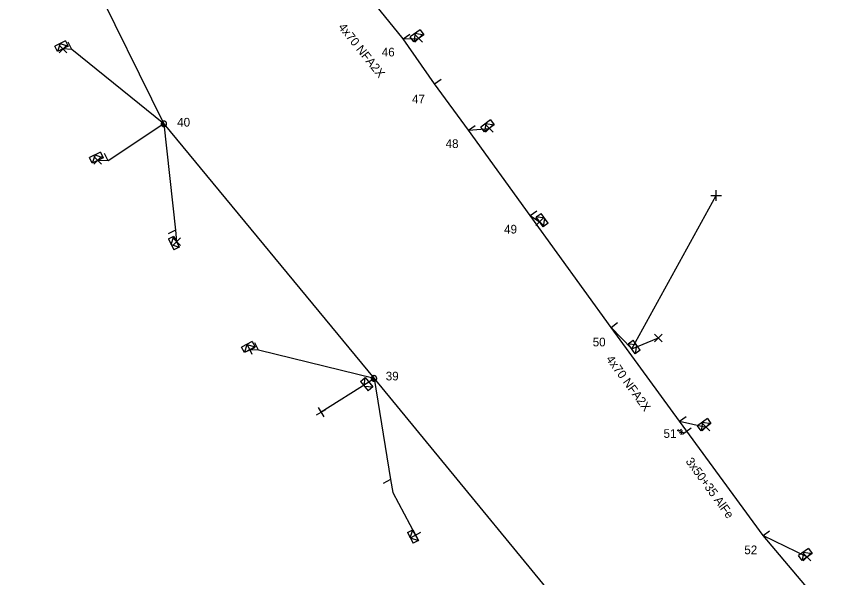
# Model space of a CAD drawing. Extents: x -536148 to -535465, y -1201639 to -1201298.
# Drawn here: x -535704.3 to -535608.3, y -1201422.6 to -1201357.9 of the extents above; entities that cross this region are included whole.
import ezdxf

# ---------------------------------------------------------------- set-up
doc = ezdxf.new("R2010")
doc.units = 0
for name, color, linetype in [('CHRAN_NN', 7, 'Continuous'), ('CIZÍ_NADZEM_POPIS', 7, 'Continuous'), ('CIZÍ_PODZEM', 7, 'Continuous'), ('DOPLŇ_POPISY', 7, 'Continuous'), ('ELE_EON', 7, 'Continuous'), ('ELE_EON_POPIS', 7, 'Continuous'), ('KN_HRAN_POHYBLIVÁ', 7, 'Continuous'), ('KN_VKP_HRAN_NEZNATELNÁ', 7, 'Continuous'), ('KN_VKP_HRAN_SPORNÁ', 7, 'Continuous'), ('NADZEM_NN_IZOL_POPIS', 7, 'Continuous'), ('PB_NN_POPIS', 7, 'Continuous'), ('PLG_EXPORT_GPE', 7, 'Continuous'), ('PODZEM_NN', 7, 'Continuous'), ('RÁMEČEK', 7, 'Continuous')]:
    doc.layers.add(name, color=color, linetype=linetype)

# ---------------------------------------------------------------- blocks, each defined once
blk = doc.blocks.new('NN440')
at = {"layer": 'ELE_EON_POPIS'}
for points in [[(0.63, 0), (0.63, 0.06), (0.62, 0.13), (0.6, 0.19), (0.58, 0.25), (0.55, 0.31), (0.51, 0.37), (0.47, 0.42), (0.42, 0.46), (0.37, 0.51), (0.32, 0.54), (0.26, 0.57), (0.2, 0.59), (0.13, 0.61), (0.07, 0.62), (0, 0.63), (-0.06, 0.62), (-0.13, 0.61), (-0.19, 0.59), (-0.26, 0.57), (-0.31, 0.54), (-0.37, 0.51), (-0.42, 0.46), (-0.47, 0.42), (-0.51, 0.37), (-0.54, 0.31), (-0.57, 0.25), (-0.6, 0.19), (-0.62, 0.13), (-0.63, 0.06), (-0.63, 0), (-0.63, -0.07), (-0.62, -0.14), (-0.6, -0.2), (-0.57, -0.26), (-0.54, -0.32), (-0.51, -0.37), (-0.47, -0.43), (-0.42, -0.47), (-0.37, -0.51), (-0.31, -0.55), (-0.26, -0.58), (-0.19, -0.6), (-0.13, -0.62), (-0.06, -0.63), (0, -0.63), (0.07, -0.63), (0.13, -0.62), (0.2, -0.6), (0.26, -0.58), (0.32, -0.55), (0.37, -0.51), (0.42, -0.47), (0.47, -0.43), (0.51, -0.37), (0.55, -0.32), (0.58, -0.26), (0.6, -0.2), (0.62, -0.14), (0.63, -0.07), (0.63, 0)], [(-0.63, 0), (0.63, 0)], [(-0.6, -0.18), (0.57, -0.18)], [(-0.51, -0.32), (0.5, -0.32)], [(-0.37, -0.47), (0.35, -0.47)]]:
    blk.add_lwpolyline(points, dxfattribs=at)
blk = doc.blocks.new('NN840')
at = {"layer": 'RÁMEČEK'}
for points in [[(0.003, 0.619), (0.003, -0.631)], [(-0.745, -0.71), (-0.745, -0.66)], [(-0.73, -0.764), (-0.745, -0.71)], [(-0.657, -0.798), (-0.73, -0.764)], [(-0.627, -0.798), (-0.657, -0.798)], [(-0.558, -0.764), (-0.627, -0.798)], [(-0.538, -0.71), (-0.558, -0.764)], [(-0.538, -0.385), (-0.538, -0.71)], [(-0.332, -0.385), (-0.332, -0.798)], [(-0.332, -0.641), (-0.125, -0.385)], [(-0.263, -0.557), (-0.091, -0.798)]]:
    blk.add_lwpolyline(points, dxfattribs=at)
blk = doc.blocks.new('NN800')
at = {"layer": 'ELE_EON'}
for points in [[(-0.442, 0.442), (0.442, -0.442)], [(-0.442, -0.442), (0.442, 0.442)]]:
    blk.add_lwpolyline(points, dxfattribs=at)
blk = doc.blocks.new('NN630')
at = {"layer": 'CIZÍ_PODZEM'}
for points in [[(-0.003, -0.7), (-0.703, 0)], [(-0.703, -0.7), (-0.703, 0), (0.697, 0), (0.697, -0.7)], [(-0.703, -0.7), (0.697, -0.7)], [(-0.003, -0.7), (0.697, 0)]]:
    blk.add_lwpolyline(points, dxfattribs=at)
blk = doc.blocks.new('NN510')
at = {"layer": 'ELE_EON_POPIS'}
blk.add_lwpolyline([(0.001, 0.002), (0.001, 0.939)], dxfattribs=at)

msp = doc.modelspace()

# ---------------------------------------------------------------- linework, layer by layer
at = {"layer": 'CHRAN_NN'}
for points in [[(-535633.32, -1201396.213), (-535623.573, -1201378.533)], [(-535633.32, -1201396.213), (-535630.235, -1201394.972)], [(-535663.633, -1201400.077), (-535669.128, -1201403.532)]]:
    msp.add_lwpolyline(points, dxfattribs=at)
at = {"layer": 'CIZÍ_NADZEM_POPIS'}
for points in [[(-535687.29, -1201370.27), (-535697.905, -1201361.707), (-535698.947, -1201361.642)], [(-535687.29, -1201370.27), (-535685.964, -1201382.55), (-535685.834, -1201383.866)], [(-535635.707, -1201393.748), (-535633.32, -1201396.213)], [(-535663.05, -1201399.63), (-535676.358, -1201396.359), (-535677.377, -1201396.325)], [(-535663.05, -1201399.63), (-535661.159, -1201411.303), (-535660.891, -1201412.779), (-535658.249, -1201417.705)], [(-535627.799, -1201404.564), (-535624.739, -1201405.25)]]:
    msp.add_lwpolyline(points, dxfattribs=at)
at = {"layer": 'ELE_EON'}
for points in [[(-535704.28, -1201335.78), (-535687.29, -1201370.27), (-535663.05, -1201399.63), (-535635.32, -1201433.41), (-535614.862, -1201457.774), (-535589.24, -1201487.744), (-535570.255, -1201520.699), (-535562.055, -1201543.241)], [(-535566.21, -1201489.133), (-535573.362, -1201479.314), (-535581.292, -1201468.256), (-535583.925, -1201464.639), (-535590.303, -1201455.917), (-535602.568, -1201439.045), (-535607.499, -1201430.342), (-535618.17, -1201417.757), (-535627.799, -1201404.564)]]:
    msp.add_lwpolyline(points, dxfattribs=at)
at = {"layer": 'NADZEM_NN_IZOL_POPIS'}
msp.add_lwpolyline([(-535627.799, -1201404.564), (-535635.707, -1201393.748), (-535645.039, -1201380.866), (-535652.143, -1201371.008), (-535656.064, -1201365.681), (-535659.686, -1201360.49), (-535664.84, -1201354.078), (-535664.841, -1201354.077)], dxfattribs=at)
at = {"layer": 'PB_NN_POPIS'}
for points in [[(-535659.686, -1201360.49), (-535657.893, -1201360.419)], [(-535687.29, -1201370.27), (-535693.734, -1201374.54), (-535694.922, -1201374.495)], [(-535652.143, -1201371.008), (-535649.743, -1201370.8)], [(-535645.039, -1201380.866), (-535643.94, -1201381.576)], [(-535663.05, -1201399.63), (-535663.633, -1201400.077)], [(-535618.17, -1201417.757), (-535613.086, -1201420.218)]]:
    msp.add_lwpolyline(points, dxfattribs=at)

# ---------------------------------------------------------------- block references
at = {"layer": 'DOPLŇ_POPISY'}
for p, rotation in [((-535659.687, -1201360.49), -54.066469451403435), ((-535697.905, -1201361.708), 26.21569160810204), ((-535656.065, -1201365.681), -54.06646942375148), ((-535652.144, -1201371.008), -54.066469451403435), ((-535693.734, -1201374.54), 26.002647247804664), ((-535645.039, -1201380.866), -54.21398046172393), ((-535685.964, -1201382.551), 116.5570527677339), ((-535635.707, -1201393.748), -54.21398048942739), ((-535676.358, -1201396.359), 29.05460272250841), ((-535627.799, -1201404.564), -54.2139805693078), ((-535661.158, -1201411.303), 118.19804171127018), ((-535618.17, -1201417.757), -54.21398054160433)]:
    msp.add_blockref('NN510', p, dxfattribs=dict(at, rotation=rotation))
at = {"layer": 'DOPLŇ_POPISY', "xscale": 0.5, "yscale": 0.5}
for p, rotation in [((-535687.29, -1201370.27), -50.48374165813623), ((-535663.05, -1201399.63), -50.57305274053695)]:
    msp.add_blockref('NN440', p, dxfattribs=dict(at, rotation=rotation))
at = {"layer": 'KN_HRAN_POHYBLIVÁ', "rotation": -53.87591111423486}
msp.add_blockref('NN840', (-535626.951, -1201405.726), dxfattribs=at)
at = {"layer": 'KN_VKP_HRAN_NEZNATELNÁ'}
for p in [(-535657.893, -1201360.419), (-535698.947, -1201361.642), (-535649.743, -1201370.8), (-535694.922, -1201374.495), (-535643.94, -1201381.576), (-535685.834, -1201383.866), (-535630.235, -1201394.972), (-535624.739, -1201405.25), (-535613.086, -1201420.218)]:
    msp.add_blockref('NN800', p, dxfattribs=at)
for p, rotation in [((-535623.573, -1201378.533), 44.999999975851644), ((-535677.377, -1201396.325), 70.03070835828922), ((-535669.128, -1201403.532), 75.7294194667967), ((-535658.249, -1201417.705), 164.06395827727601)]:
    msp.add_blockref('NN800', p, dxfattribs=dict(at, rotation=rotation))
at = {"layer": 'KN_VKP_HRAN_SPORNÁ'}
for p, rotation in [((-535657.893, -1201360.419), -145.71327212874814), ((-535698.947, -1201361.642), -153.78551115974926), ((-535649.743, -1201370.8), -143.6395471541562), ((-535694.922, -1201374.495), -154.00398898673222), ((-535643.94, -1201381.576), 125.86873882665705), ((-535685.834, -1201383.866), -63.40905549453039), ((-535677.377, -1201396.325), -151.16610838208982), ((-535633.32, -1201396.213), 126.10046113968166), ((-535663.633, -1201400.076), -50.60113056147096), ((-535624.739, -1201405.25), -143.7744472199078), ((-535658.249, -1201417.705), -61.818925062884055), ((-535613.086, -1201420.218), -143.917683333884)]:
    msp.add_blockref('NN630', p, dxfattribs=dict(at, rotation=rotation))

# ---------------------------------------------------------------- texts
at = {"layer": 'ELE_EON_POPIS'}
msp.add_text('3x50+35 AlFe', height=1, rotation=306.124, dxfattribs=at).set_placement((-535627.143, -1201409.205))
at = {"layer": 'PLG_EXPORT_GPE'}
for s, p in [('46', (-535662.153, -1201362.502)), ('47', (-535658.664, -1201367.915)), ('40', (-535685.756, -1201370.591)), ('48', (-535654.789, -1201373.065)), ('49', (-535648.039, -1201382.923)), ('50', (-535637.818, -1201395.938)), ('39', (-535661.693, -1201399.863)), ('51', (-535629.644, -1201406.487)), ('52', (-535620.326, -1201419.903))]:
    msp.add_text(s, height=1, dxfattribs=at).set_placement(p)
at = {"layer": 'PODZEM_NN'}
for rotation, p in [(308.793, (-535667.228, -1201359.156)), (306.172, (-535636.326, -1201397.415))]:
    msp.add_text('4x70 NFA2X', height=1, rotation=rotation, dxfattribs=at).set_placement(p)

doc.saveas('drawing.dxf')
